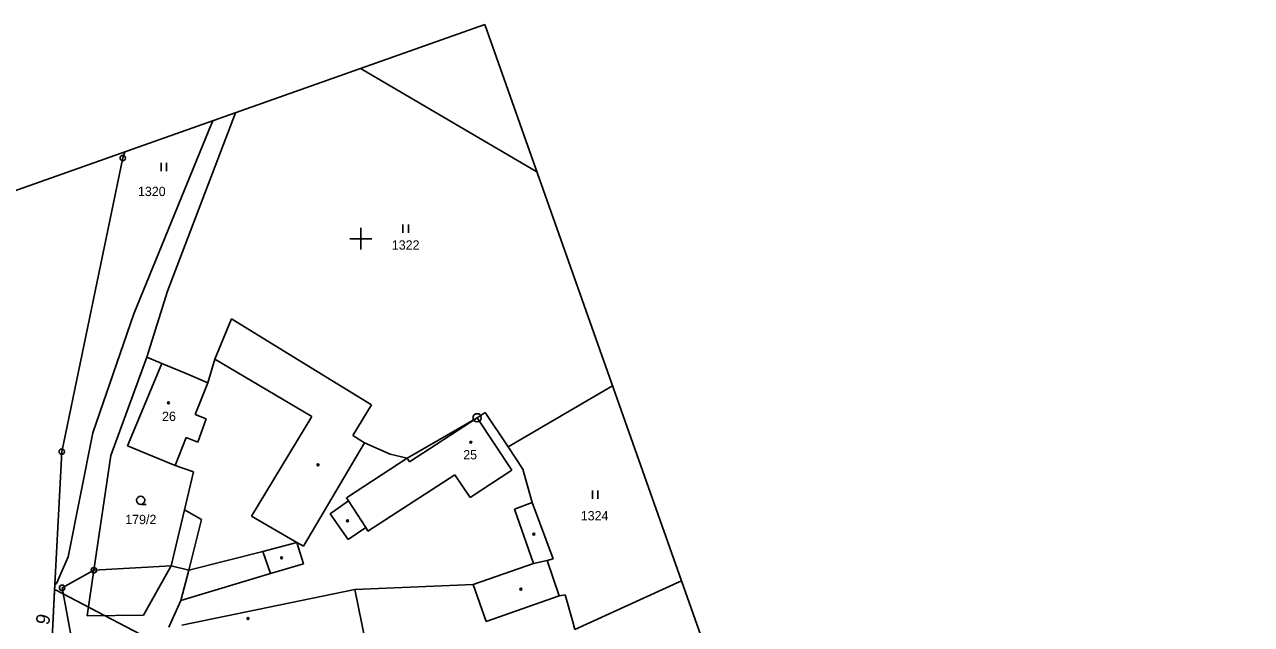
# Model space of a CAD drawing. Extents: x -779950 to -779537, y -1100753 to -1100261.
# Drawn here: x -779761.4 to -779537.4, y -1100370.4 to -1100260.9 of the extents above; entities that cross this region are included whole.
import ezdxf

# ---------------------------------------------------------------- set-up
doc = ezdxf.new("R2010")
doc.units = 0
for name, color, linetype in [('BPEJ', 7, 'Continuous'), ('Groma (60)', 7, 'Continuous'), ('Katastr_HRANICE DRÁHY', 7, 'Continuous'), ('Katastr_Hranice parcel', 7, 'Continuous'), ('Katastr_Parcelní čísla', 7, 'Continuous'), ('Katastr_Slučkované čáry', 7, 'Continuous'), ('Katastr_Značky kultur', 7, 'Continuous'), ('čtvercová síť', 7, 'Continuous')]:
    doc.layers.add(name, color=color, linetype=linetype)

# ---------------------------------------------------------------- blocks, each defined once
blk = doc.blocks.new('C691')
at = {"layer": 'čtvercová síť'}
for p, q in [((-0.5, 0), (0.5, 0)), ((0, 0.5), (0, -0.5))]:
    blk.add_line(p, q, dxfattribs=at)

msp = doc.modelspace()

# ---------------------------------------------------------------- linework, layer by layer
at = {"layer": 'BPEJ'}
for points in [[(-779755.9, -1100364.14), (-779755.85, -1100363.13), (-779754.6, -1100338.89), (-779743.46, -1100285.26), (-779743.1, -1100284.14)], [(-779625.47, -1100688.02), (-779650.47, -1100650.42), (-779681.32, -1100605.77), (-779703.57, -1100572.42), (-779721.36, -1100542.95), (-779739.67, -1100497.93), (-779743.7, -1100484.06), (-779744.94, -1100484.43), (-779746.21, -1100480.3), (-779744.9, -1100479.92), (-779754.11, -1100448.23), (-779757.39, -1100424.96), (-779758.99, -1100393.31), (-779756.39, -1100373.64), (-779756.29, -1100371.78), (-779755.9, -1100364.14)], [(-779755.9, -1100364.14), (-779755.75, -1100364.13), (-779735.18, -1100374.9)]]:
    msp.add_lwpolyline(points, dxfattribs=at)
at = {"layer": 'Defpoints'}
for p, q in [((-779677.36, -1100260.91), (-779949.84, -1100357.2)), ((-779537.42, -1100656.91), (-779677.36, -1100260.91))]:
    msp.add_line(p, q, dxfattribs=at)
at = {"layer": 'Katastr_HRANICE DRÁHY'}
for points in [[(-779743.46, -1100285.26), (-779754.6, -1100338.89)], [(-779743.1, -1100284.14), (-779743.46, -1100285.26)], [(-779754.6, -1100338.89), (-779755.85, -1100363.13)], [(-779755.85, -1100363.13), (-779756.29, -1100371.78)]]:
    msp.add_lwpolyline(points, dxfattribs=at)
at = {"layer": 'Katastr_Hranice parcel'}
for points in [[(-779700.09, -1100268.94), (-779698.93, -1100269.62)], [(-779698.93, -1100269.62), (-779667.86, -1100287.77)], [(-779735.29, -1100309.6), (-779722.9, -1100277)], [(-779727.03, -1100278.46), (-779727.72, -1100280.05)], [(-779727.72, -1100280.05), (-779741.43, -1100313.7)], [(-779739.07, -1100321.62), (-779735.29, -1100309.6)], [(-779741.43, -1100313.7), (-779748.93, -1100335.45)], [(-779726.65, -1100322.01), (-779723.64, -1100314.61)], [(-779723.64, -1100314.61), (-779710.66, -1100322.58)], [(-779745.66, -1100339.59), (-779739.07, -1100321.62)], [(-779736.36, -1100322.76), (-779742.6, -1100337.82)], [(-779739.07, -1100321.62), (-779736.36, -1100322.76)], [(-779736.36, -1100322.76), (-779731.89, -1100324.64)], [(-779727.94, -1100326.3), (-779726.65, -1100322.01)], [(-779710.66, -1100322.58), (-779698.03, -1100330.3)], [(-779731.89, -1100324.64), (-779727.94, -1100326.3)], [(-779673.12, -1100338.02), (-779654.04, -1100326.89)], [(-779698.03, -1100330.3), (-779701.48, -1100335.94)], [(-779678.77, -1100332.7), (-779677.29, -1100331.75)], [(-779677.29, -1100331.75), (-779673.12, -1100338.02)], [(-779691.54, -1100340.08), (-779678.77, -1100332.7)], [(-779748.93, -1100335.45), (-779753.4, -1100358.07)], [(-779701.48, -1100335.94), (-779699.32, -1100337.25)], [(-779742.6, -1100337.82), (-779733.92, -1100341.4)], [(-779699.32, -1100337.25), (-779710.47, -1100356.15)], [(-779699.32, -1100337.25), (-779694.64, -1100339.33)], [(-779673.12, -1100338.02), (-779670.43, -1100342.07)], [(-779748.74, -1100360.52), (-779745.66, -1100339.59)], [(-779733.92, -1100341.4), (-779730.56, -1100342.58)], [(-779694.64, -1100339.33), (-779691.54, -1100340.08)], [(-779730.56, -1100342.58), (-779732.21, -1100349.5)], [(-779670.43, -1100342.07), (-779668.7, -1100348.13)], [(-779668.7, -1100348.13), (-779664.92, -1100358.47)], [(-779732.21, -1100349.5), (-779734.65, -1100359.73)], [(-779732.21, -1100349.5), (-779729.07, -1100351.26)], [(-779729.07, -1100351.26), (-779731.4, -1100360.51)], [(-779717.92, -1100357.13), (-779731.4, -1100360.51)], [(-779717.92, -1100357.13), (-779711.68, -1100355.45)], [(-779711.68, -1100355.45), (-779710.47, -1100356.15)], [(-779753.4, -1100358.07), (-779755.58, -1100362.94)], [(-779664.92, -1100358.47), (-779665.98, -1100358.77)], [(-779665.98, -1100358.77), (-779663.79, -1100365.19)], [(-779754.54, -1100363.74), (-779748.74, -1100360.52)], [(-779748.74, -1100360.52), (-779734.65, -1100359.73)], [(-779731.4, -1100360.51), (-779732.89, -1100366.08)], [(-779755.58, -1100362.94), (-779755.85, -1100363.13)], [(-779748.79, -1100394.62), (-779754.54, -1100363.74)], [(-779701.1, -1100364.07), (-779679.49, -1100363.1)], [(-779679.49, -1100363.1), (-779677.11, -1100369.87)], [(-779641.48, -1100362.43), (-779660.95, -1100371.32)], [(-779732.89, -1100366.08), (-779735.04, -1100370.94)], [(-779701.1, -1100364.07), (-779732.67, -1100370.55)], [(-779698.54, -1100376.59), (-779701.1, -1100364.07)], [(-779677.11, -1100369.87), (-779663.79, -1100365.19)], [(-779663.79, -1100365.19), (-779662.73, -1100365)], [(-779662.73, -1100365), (-779661.32, -1100369.94)], [(-779661.32, -1100369.94), (-779660.95, -1100371.32)]]:
    msp.add_lwpolyline(points, dxfattribs=at)
at = {"layer": 'Katastr_Slučkované čáry'}
for points in [[(-779726.65, -1100322.01), (-779708.93, -1100332.46)], [(-779727.94, -1100326.3), (-779730.23, -1100332.08)], [(-779730.23, -1100332.08), (-779728.22, -1100332.88)], [(-779708.93, -1100332.46), (-779719.94, -1100350.65)], [(-779728.22, -1100332.88), (-779729.78, -1100337.15)], [(-779691.1, -1100340.75), (-779678.77, -1100332.7)], [(-779672.46, -1100342.24), (-779678.77, -1100332.7)], [(-779731.89, -1100336.28), (-779733.92, -1100341.4)], [(-779729.78, -1100337.15), (-779731.89, -1100336.28)], [(-779702.63, -1100347.3), (-779691.54, -1100340.08)], [(-779691.1, -1100340.75), (-779691.54, -1100340.08)], [(-779698.71, -1100353.37), (-779682.82, -1100343.11)], [(-779682.82, -1100343.11), (-779680.03, -1100347.23)], [(-779680.03, -1100347.23), (-779672.46, -1100342.24)], [(-779705.61, -1100350.21), (-779702.26, -1100347.88)], [(-779702.26, -1100347.88), (-779702.63, -1100347.3)], [(-779702.26, -1100347.88), (-779699.12, -1100352.74)], [(-779668.7, -1100348.13), (-779671.98, -1100349.38)], [(-779702.31, -1100354.93), (-779705.61, -1100350.21)], [(-779671.98, -1100349.38), (-779668.51, -1100359.27)], [(-779719.94, -1100350.65), (-779711.68, -1100355.45)], [(-779699.12, -1100352.74), (-779702.31, -1100354.93)], [(-779698.71, -1100353.37), (-779699.12, -1100352.74)], [(-779717.92, -1100357.13), (-779716.47, -1100361.14)], [(-779710.45, -1100359.36), (-779711.68, -1100355.45)], [(-779716.47, -1100361.14), (-779710.45, -1100359.36)], [(-779668.51, -1100359.27), (-779679.49, -1100363.1)], [(-779668.51, -1100359.27), (-779665.98, -1100358.77)], [(-779749.97, -1100368.85), (-779748.74, -1100360.52)], [(-779734.65, -1100359.73), (-779739.68, -1100368.73)], [(-779734.65, -1100359.73), (-779731.4, -1100360.51)], [(-779732.89, -1100366.08), (-779716.47, -1100361.14)], [(-779739.68, -1100368.73), (-779749.97, -1100368.85)]]:
    msp.add_lwpolyline(points, dxfattribs=at)
at = {"layer": 'Katastr_Značky kultur'}
for p, q in [((-779743.51, -1100285.26), (-779743.41, -1100285.26)), ((-779736.48, -1100286.15), (-779736.48, -1100287.65)), ((-779735.48, -1100287.65), (-779735.48, -1100286.15)), ((-779692.33, -1100297.41), (-779692.33, -1100298.91)), ((-779691.33, -1100298.91), (-779691.33, -1100297.41)), ((-779678.82, -1100332.7), (-779678.72, -1100332.7)), ((-779754.65, -1100338.89), (-779754.55, -1100338.89)), ((-779657.72, -1100345.99), (-779657.72, -1100347.49)), ((-779656.72, -1100347.49), (-779656.72, -1100345.99)), ((-779740.19, -1100348.5), (-779739.19, -1100348.5)), ((-779748.79, -1100360.52), (-779748.69, -1100360.52)), ((-779754.59, -1100363.74), (-779754.49, -1100363.74))]:
    msp.add_line(p, q, dxfattribs=at)
for centre, radius in [((-779743.46, -1100285.26), 0.499), ((-779735.12, -1100329.97), 0.175), ((-779678.77, -1100332.7), 0.756), ((-779679.94, -1100337.17), 0.175), ((-779754.6, -1100338.89), 0.499), ((-779707.82, -1100341.28), 0.175), ((-779740.19, -1100347.75), 0.75), ((-779702.42, -1100351.52), 0.175), ((-779668.44, -1100353.94), 0.175), ((-779714.46, -1100358.24), 0.175), ((-779748.74, -1100360.52), 0.499), ((-779754.54, -1100363.74), 0.499), ((-779670.78, -1100363.99), 0.175), ((-779720.6, -1100369.34), 0.175)]:
    msp.add_circle(centre, radius, dxfattribs=at)

# ---------------------------------------------------------------- block references
at = {"layer": 'čtvercová síť', "xscale": 4, "yscale": 4}
msp.add_blockref('C691', (-779700, -1100300), dxfattribs=at)

# ---------------------------------------------------------------- texts
at = {"layer": 'Groma (60)'}
msp.add_text('9', height=2.5, rotation=76.9262, dxfattribs=at).set_placement((-779757.01, -1100370.67))
at = {"layer": 'Katastr_Parcelní čísla'}
for s, p in [('1320', (-779740.69, -1100292.22)), ('1322', (-779694.35, -1100302)), ('26', (-779736.29, -1100333.28)), ('25', (-779681.31, -1100340.29)), ('179/2', (-779743.01, -1100352.11)), ('1324', (-779659.86, -1100351.43))]:
    msp.add_text(s, height=1.7, dxfattribs=at).set_placement(p)

doc.saveas('drawing.dxf')
